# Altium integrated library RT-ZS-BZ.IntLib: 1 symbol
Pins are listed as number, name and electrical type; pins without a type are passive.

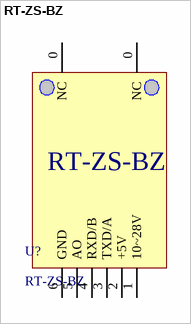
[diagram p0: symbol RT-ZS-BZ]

## RT-ZS-BZ
designator U?
NoiseModle
footprint RT-ZS-BZ
pins: 0 NC, 0 NC, 1 10~28V, 2 +5V, 3 TXD/A, 4 RXD/B, 5 AO, 6 GND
